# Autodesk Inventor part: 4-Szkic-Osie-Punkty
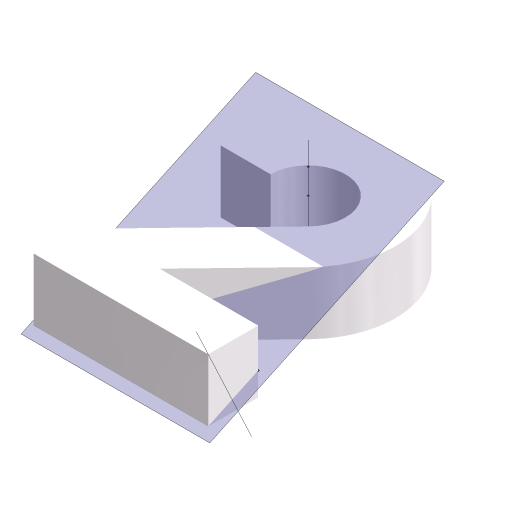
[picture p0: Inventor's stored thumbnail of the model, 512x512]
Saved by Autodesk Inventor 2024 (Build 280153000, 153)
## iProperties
Company: ATC
Shininess: 21.0
Length Units: 11269
Angle Units: 11279
Time Units: 11290
Mass Units: 11283
Length Display Precision: 3
Angle Display Precision: 2
Compacted: True
Created: 2023-03
Part Number: 4-Szkic-Osie-Punkty
Document SubType Name: Modeling
Designer: Andrzej Jaskulski
Material: Kurs-AJ
Density: 1 g/cm^3
Appearance: Kurs-AJ
Checked By: A.J.
Engr Approved By: Andrzej Jaskulski
Mfg Approved By: Andrzej Jaskulski
Authority: A.J.
Density: 0.0
Volumn: 0.0
Area: 0.0
PropertySet Name: Model Information
Control State: 0
Master: False
Checked Out: False
Title: A.J.: Kurs R2024-MEP
Author: Andrzej Jaskulski
Revision Number: 1/24
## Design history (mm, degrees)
sketch "Zarys dwójki"
  geometry: L1 (140, 0.063)-(0, 0.063) reference; L2 (0, 0.063)-(0, 34.389) reference; L3 (0, 150.063)-(40, 150.063); L4 (140, 0.063)-(140, 40.063); L5 (140, 40.063)-(61.086, 40.063); L6 (61.086, 40.063)-(120.354, 101.437); L7 (91.58, 129.223)-(0, 34.389); A1 r 30 centre (70, 150.063) between (91.58, 129.223) and (40, 150.063); A2 r 70 centre (70, 150.063) between (120.354, 101.437) and (0, 150.063)
  constraints: 14 end point, 4 perpendicular, 4 point on circle, 2 centre point, 2 parallel, 2 tangent, 1 coincident
  dimensions: "d0" = 140 distance of L1.start L1.end; "d1" = 150 vertical distance of A1.centre L1.end; "d2" = 70 horizontal distance of L1.end A1.centre; "d3" = 46 deg angle of L6 L5; "d4" = 150 distance of L3.start L1.end (= d1); "d5" = 30 radius of A1; "d6" = 70 radius of A2
extrude "Dwójka" new body sketch "Zarys dwójki" distance "d7" = 50; taper "d8" = 0 deg
node "Nad Dwójką"
node "Prostopadła do płaszczyzny"
node "Oś walca"
node "Punkt przebicia osią płaszczyzny konstrukcyjnej"
node "Punkt przebicia osią powierzchni dwójki"
node "Punkt przebicia krawędzią"
node "Bryła1"
node "Korpusy bryłowe"
node "Korpusy powierzchniowe"
other parameters: "d9" = 90 deg, "d14" = -35 deg, "d16" = -25 deg, "d17" = -25 deg
